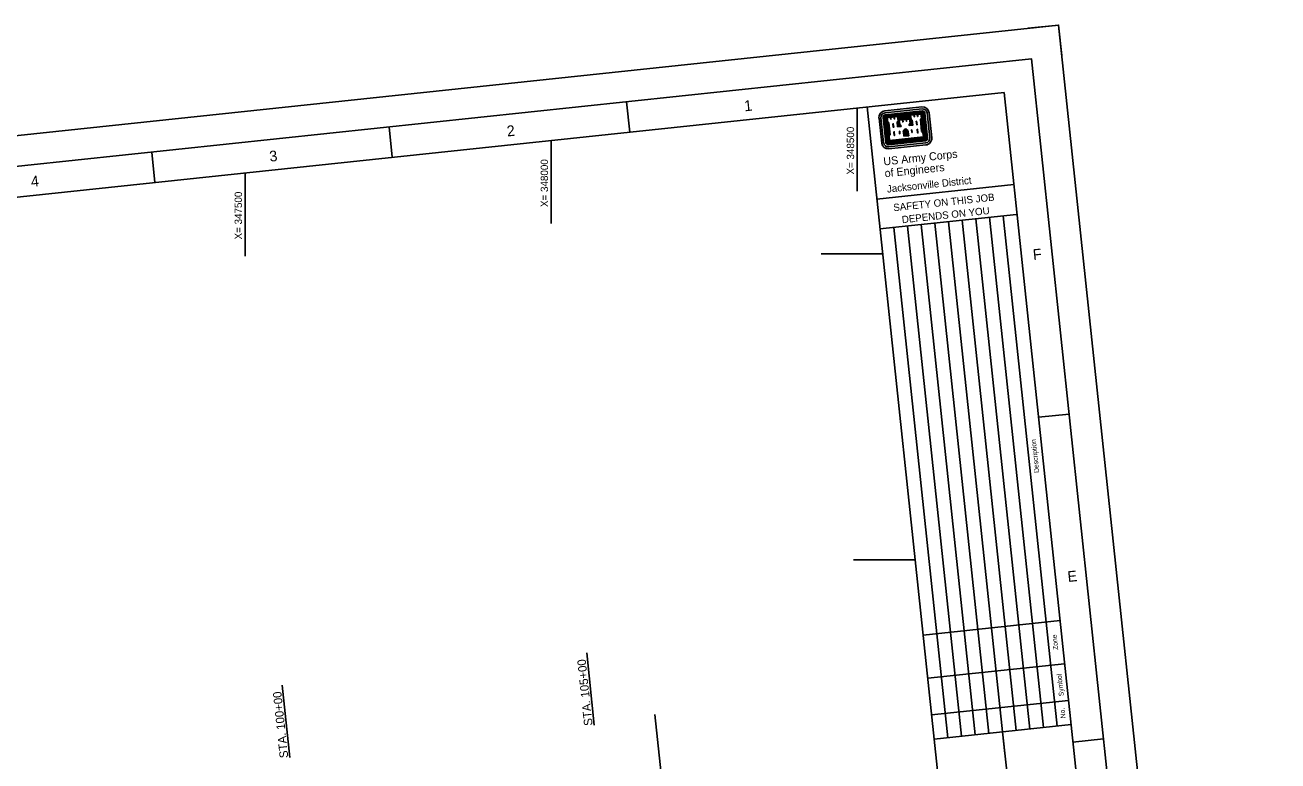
# Model space of a CAD drawing. Extents: x 344453 to 349187, y 1184529 to 1188374.
# Drawn here: x 347141 to 349187, y 1187172 to 1188374 of the extents above; entities that cross this region are included whole.
import ezdxf

# ---------------------------------------------------------------- set-up
doc = ezdxf.new("R2010")
doc.units = 0
for name, color, linetype in [('G-ANNO-NPLT', 7, 'Continuous'), ('G-ANNO-TEXT-LOGO', 7, 'Continuous'), ('G-ANNO-TEXT-TTLB', 7, 'Continuous'), ('G-ANNO-TTLB', 7, 'Continuous'), ('V-ALGN-TEXT', 7, 'Continuous'), ('V-ANNO-MATC', 7, 'Continuous'), ('V-TOPO-COOR-STAT', 7, 'Continuous')]:
    doc.layers.add(name, color=color, linetype=linetype)

msp = doc.modelspace()

# ---------------------------------------------------------------- linework, layer by layer
at = {"layer": 'G-ANNO-NPLT'}
msp.add_lwpolyline([(344453.5, 1187909.7), (348828.9, 1188373.5), (349187.3, 1184992.5), (344811.8, 1184528.7)], close=True, dxfattribs=at)
msp.add_lwpolyline([(348834.2, 1188323.8), (348828.9, 1188373.5), (348779.2, 1188368.3)], dxfattribs=at)
at = {"layer": 'G-ANNO-TEXT-LOGO'}
for p, q in [((348605.6, 1188239.9), (348545.2, 1188233.5)), ((348545.5, 1188230.3), (348606, 1188236.7)), ((348535.7, 1188221.7), (348540, 1188180.9)), ((348543.2, 1188181.3), (348538.8, 1188222)), ((348542.3, 1188222.4), (348546.6, 1188181.6)), ((348543.2, 1188222.5), (348547.5, 1188181.7)), ((348544, 1188222.6), (348548.3, 1188181.8)), ((348544.9, 1188222.7), (348549.2, 1188181.9)), ((348545.8, 1188222.8), (348550.1, 1188182)), ((348606.3, 1188233.3), (348545.9, 1188226.9)), ((348606.4, 1188232.4), (348546, 1188226)), ((348606.5, 1188231.5), (348546.1, 1188225.1)), ((348606.6, 1188230.7), (348546.1, 1188224.3)), ((348606.7, 1188229.8), (348546.2, 1188223.4)), ((348546.7, 1188222.9), (348551, 1188182.4)), ((348547.5, 1188222.9), (348551.7, 1188183.4)), ((348567.3, 1188224.8), (348585.8, 1188226.8)), ((348567.4, 1188223.9), (348585.9, 1188225.9)), ((348567.5, 1188223.2), (348586, 1188225.1)), ((348567.6, 1188222.3), (348586.1, 1188224.2)), ((348567.7, 1188221.4), (348586.2, 1188223.3)), ((348567.8, 1188220.6), (348586.3, 1188222.5)), ((348567.9, 1188219.7), (348586.3, 1188221.6)), ((348605, 1188219.4), (348607, 1188200.4)), ((348605.6, 1188229.1), (348609.8, 1188189.5)), ((348605.8, 1188220.3), (348608, 1188199.6)), ((348606.4, 1188229.2), (348610.7, 1188188.7)), ((348607.3, 1188229.3), (348611.6, 1188188.5)), ((348608.2, 1188229.4), (348612.5, 1188188.6)), ((348608.9, 1188229.5), (348613.3, 1188188.7)), ((348609.8, 1188229.6), (348614.2, 1188188.8)), ((348610.7, 1188229.6), (348615.1, 1188188.9)), ((348614.1, 1188230), (348618.4, 1188189.2)), ((348621.7, 1188189.6), (348617.4, 1188230.4)), ((348549.1, 1188214.4), (348551.3, 1188193.5)), ((348550.1, 1188213.6), (348552.1, 1188194.6)), ((348576.1, 1188191.9), (348575.4, 1188198.6)), ((348576.9, 1188192), (348576.2, 1188198.6)), ((348577.8, 1188192.1), (348577.1, 1188198.7)), ((348578.7, 1188192.2), (348578, 1188198.8)), ((348579.5, 1188192.2), (348578.8, 1188198.9)), ((348580.7, 1188192.4), (348580, 1188199)), ((348581.5, 1188192.5), (348580.8, 1188199.1)), ((348582.4, 1188192.6), (348581.7, 1188199.2)), ((348583.3, 1188192.6), (348582.6, 1188199.3)), ((348584.1, 1188192.7), (348583.4, 1188199.4)), ((348611.1, 1188187.9), (348550.7, 1188181.4)), ((348611.2, 1188187.1), (348550.8, 1188180.7)), ((348611.3, 1188186.2), (348550.9, 1188179.8)), ((348610.7, 1188188.7), (348551, 1188182.4)), ((348611.4, 1188185.3), (348551, 1188178.9)), ((348611.5, 1188184.5), (348551, 1188178.1)), ((348611.9, 1188181), (348551.4, 1188174.6)), ((348609.8, 1188189.5), (348551.7, 1188183.4)), ((348551.8, 1188171.3), (348612.2, 1188177.7)), ((348576.1, 1188191.9), (348584.1, 1188192.7))]:
    msp.add_line(p, q, dxfattribs=at)
for points in [[(348548.2, 1188223), (348549, 1188215.2), (348550.9, 1188213.6), (348552.9, 1188194.7), (348551.4, 1188192.7), (348552.3, 1188184), (348609, 1188190), (348608.1, 1188198.7), (348606.1, 1188200.3), (348604.1, 1188219.3), (348605.7, 1188221.2), (348604.9, 1188229), (348597.4, 1188228.2), (348591.6, 1188227.6), (348586.3, 1188227.1), (348587.1, 1188219.2), (348589.2, 1188217.7), (348589.9, 1188210.7), (348585.7, 1188210.3), (348585.7, 1188211), (348587.3, 1188213), (348586.4, 1188220.7), (348579, 1188219.9), (348573.2, 1188219.3), (348567.9, 1188218.8), (348568.8, 1188211), (348570.7, 1188209.4), (348570.8, 1188208.7), (348566.6, 1188208.3), (348565.9, 1188215.2), (348567.5, 1188217.1), (348566.7, 1188225), (348559.2, 1188224.2), (348553.5, 1188223.6), (348548.2, 1188223)], [(348549.1, 1188222.2), (348549.8, 1188215.6), (348551.8, 1188214), (348553.8, 1188194.4), (348552.2, 1188192.4), (348553, 1188185), (348608.1, 1188190.9), (348607.3, 1188198.2), (348605.3, 1188199.8), (348603.2, 1188219.5), (348604.9, 1188221.5), (348604.2, 1188228), (348598.8, 1188227.5), (348599.1, 1188224.4), (348598.6, 1188224.3), (348598.3, 1188227.4), (348593, 1188226.9), (348593.4, 1188223.8), (348593, 1188223.7), (348592.6, 1188226.8), (348587.3, 1188226.3), (348588, 1188219.7), (348589.9, 1188218.1), (348590.8, 1188210), (348585, 1188209.4), (348584.8, 1188211.3), (348586.4, 1188213.3), (348585.7, 1188219.9), (348580.4, 1188219.3), (348580.7, 1188216.2), (348580.3, 1188216.2), (348580, 1188219.2), (348574.6, 1188218.7), (348574.9, 1188215.6), (348574.4, 1188215.5), (348574.1, 1188218.6), (348568.8, 1188218.1), (348569.5, 1188211.5), (348571.5, 1188209.9), (348571.7, 1188208), (348565.9, 1188207.4), (348565.1, 1188215.5), (348566.7, 1188217.4), (348566, 1188224), (348560.7, 1188223.4), (348561, 1188220.4), (348560.5, 1188220.3), (348560.2, 1188223.4), (348554.8, 1188222.8), (348555.2, 1188219.7), (348554.8, 1188219.7), (348554.5, 1188222.8), (348549.1, 1188222.2)], [(348567.3, 1188215.5), (348566.8, 1188214.9), (348567.4, 1188209.3), (348569.3, 1188209.5), (348567.9, 1188210.6), (348567.4, 1188215.6)], [(348587.8, 1188217.7), (348588.3, 1188217.2), (348588.9, 1188211.5), (348587.1, 1188211.4), (348588.2, 1188212.8), (348587.7, 1188217.7)], [(348597, 1188216.5), (348597.7, 1188210.8), (348597.2, 1188210.7), (348596.5, 1188216.5), (348597, 1188216.5)], [(348558.4, 1188212.4), (348559, 1188206.7), (348559.6, 1188206.7), (348559, 1188212.5), (348558.4, 1188212.4)], [(348559.8, 1188199.2), (348560.4, 1188193.3), (348561, 1188193.4), (348560.4, 1188199.3), (348559.8, 1188199.2)], [(348568.9, 1188200.2), (348569.3, 1188196.1), (348569.8, 1188196.1), (348569.4, 1188200.2), (348568.9, 1188200.2)], [(348589.4, 1188202.3), (348589.8, 1188198.3), (348589.3, 1188198.2), (348588.9, 1188202.3), (348589.4, 1188202.3)], [(348598.4, 1188203.3), (348599.1, 1188197.4), (348598.6, 1188197.4), (348598, 1188203.3), (348598.4, 1188203.3)]]:
    msp.add_lwpolyline(points, dxfattribs=at)
for centre, major_axis, start_param, end_param in [((348606.7, 1188229.2), (10.7, 1.1), 6.283169, 7.853965), ((348606.7, 1188229.2), (7.45, 0.79), 6.28317, 7.853966), ((348546.3, 1188222.8), (10.7, 1.1), 1.57078, 3.141576), ((348546.3, 1188222.8), (7.45, 0.79), 1.57078, 3.141576), ((348546.3, 1188222.8), (4, 0.42), 1.57078, 3.141576), ((348546.3, 1188222.8), (3.13, 0.33), 1.57078, 3.141576), ((348546.3, 1188222.8), (2.27, 0.24), 1.57078, 3.141576), ((348546.3, 1188222.8), (1.41, 0.15), 1.57078, 3.141576), ((348546.3, 1188222.8), (0.543, 0.058), 1.57078, 3.141576), ((348606.7, 1188229.2), (4, 0.42), 6.283169, 7.853965), ((348606.7, 1188229.2), (3.13, 0.33), 6.283169, 7.853965), ((348606.7, 1188229.2), (2.27, 0.24), 6.283169, 7.853965), ((348606.7, 1188229.2), (1.41, 0.15), 6.283169, 7.853965), ((348606.7, 1188229.2), (0.543, 0.058), 6.283169, 7.853965), ((348580.9, 1188198.7), (-5.52, -0.59), 4.985832, 6.214359), ((348580.9, 1188198.7), (-4.66, -0.49), 4.947465, 6.21436), ((348580.9, 1188198.7), (-3.8, -0.4), 4.947465, 6.21436), ((348580.9, 1188198.7), (-2.93, -0.31), 4.947465, 6.21436), ((348577.9, 1188198.4), (2.07, 0.22), 0.068794, 1.335689), ((348577.9, 1188198.4), (2.93, 0.31), 0.068794, 1.335689), ((348577.9, 1188198.4), (3.8, 0.4), 0.068795, 1.335689), ((348577.9, 1188198.4), (4.66, 0.49), 0.068795, 1.335689), ((348580.9, 1188198.7), (-2.07, -0.22), 4.947465, 6.214359), ((348577.9, 1188198.4), (5.52, 0.59), 0.068795, 1.29842), ((348550.7, 1188182), (-10.7, -1.1), 6.28317, 7.853966), ((348550.7, 1188182), (-7.45, -0.79), 6.28317, 7.853966), ((348550.7, 1188182), (-4, -0.42), 6.28317, 7.853966), ((348550.7, 1188182), (-3.13, -0.33), 6.28317, 7.853966), ((348550.7, 1188182), (-2.27, -0.24), 6.28317, 7.853966), ((348550.7, 1188182), (-1.41, -0.15), 6.28317, 7.853966), ((348550.7, 1188182), (-0.543, -0.058), 6.28317, 7.853966), ((348611, 1188188.4), (0.543, 0.058), 4.712373, 6.28317), ((348611, 1188188.4), (1.41, 0.15), 4.712373, 6.28317), ((348611, 1188188.4), (2.27, 0.24), 4.712373, 6.28317), ((348611, 1188188.4), (4, 0.42), 4.712373, 6.28317), ((348611, 1188188.4), (3.13, 0.33), 4.712373, 6.28317), ((348611, 1188188.4), (-7.45, -0.79), 1.570781, 3.141577), ((348611, 1188188.4), (10.7, 1.1), 4.712373, 6.28317)]:
    msp.add_ellipse(centre, major_axis=major_axis, ratio=0.99964, start_param=start_param, end_param=end_param, dxfattribs=at)
at = {"layer": 'G-ANNO-TTLB'}
for p, q in [((348123.2, 1188248.4), (348128.5, 1188198.7)), ((348516.3, 1188239.8), (348853.6, 1185057.7)), ((347735.4, 1188207.3), (347740.6, 1188157.6)), ((347347.5, 1188166.2), (347352.8, 1188116.5)), ((348532.2, 1188089.4), (348756, 1188113.2)), ((348536.8, 1188040.5), (348760.5, 1188064.2)), ((348649.1, 1188052.4), (348737.4, 1187219.2)), ((348671.5, 1188054.8), (348759.8, 1187221.6)), ((348693.8, 1188057.2), (348782.2, 1187223.9)), ((348716.2, 1188059.6), (348804.5, 1187226.3)), ((348738.6, 1188061.9), (348826.9, 1187228.7)), ((348559.6, 1188042.9), (348647.9, 1187209.7)), ((348582, 1188045.3), (348670.3, 1187212.1)), ((348604.3, 1188047.7), (348692.7, 1187214.4)), ((348626.7, 1188050.1), (348715, 1187216.8)), ((348846, 1187738.3), (348796.3, 1187733)), ((348607.7, 1187377.4), (348831.4, 1187401.1)), ((348615.2, 1187306.7), (348838.9, 1187330.4)), ((348621.5, 1187247), (348845.3, 1187270.7)), ((348625.7, 1187207.4), (348849.5, 1187231.1)), ((348827.5, 1186364.4), (348737.6, 1187219.2)), ((348737.6, 1187219.2), (348741.3, 1187184)), ((348902.2, 1187208), (348852.5, 1187202.7))]:
    msp.add_line(p, q, dxfattribs=at)
for points in [[(344856.3, 1184583.7), (349132.3, 1185036.9), (348784.5, 1188318.5), (344508.5, 1187865.3)], [(348740, 1188263.6), (344638, 1187828.7), (344975.3, 1184646.6), (349077.3, 1185081.4)]]:
    msp.add_lwpolyline(points, close=True, dxfattribs=at)
at = {"layer": 'V-ALGN-TEXT'}
for p, q in [((348070.6, 1187230.3), (348058.1, 1187348.2)), ((347573.4, 1187177.6), (347560.9, 1187295.5))]:
    msp.add_line(p, q, dxfattribs=at)
at = {"layer": 'V-ANNO-MATC'}
msp.add_line((348306.4, 1185955), (348169.3, 1187247.7), dxfattribs=at)
at = {"layer": 'V-TOPO-COOR-STAT'}
for p, q in [((348500, 1188102.4), (348500, 1188238.1)), ((348000, 1188049.4), (348000, 1188185.1)), ((347500, 1187996.4), (347500, 1188132.1)), ((348441.1, 1188000), (348541.7, 1188000)), ((348494.1, 1187500), (348594.7, 1187500))]:
    msp.add_line(p, q, dxfattribs=at)

# ---------------------------------------------------------------- texts
at = {"layer": 'G-ANNO-TEXT-TTLB'}
for s, height, rotation, p in [('US Army Corps', 13.086, 6.0506, (348543.5, 1188144.2)), ('of Engineers', 13.086, 6.0506, (348545.5, 1188124.9)), ('Jacksonville District', 11.9, 6.0506, (348549.2, 1188099.8)), ('SAFETY ON THIS JOB', 11.9, 6.0506, (348559.6, 1188069.4)), ('DEPENDS ON YOU', 11.9, 6.0506, (348573.5, 1188049.8)), ('Description', 8, 96.0506, (348797.4, 1187642.6)), ('Zone', 8, 96.0506, (348828.4, 1187353.5)), ('Symbol', 8, 96.0506, (348837.6, 1187277.8)), ('No.', 8, 96.0506, (348840.4, 1187241.8))]:
    msp.add_text(s, height=height, rotation=rotation, dxfattribs=at).set_placement(p)
at = {"layer": 'G-ANNO-TTLB'}
for s, p in [('1', (348316.3, 1188232.6)), ('2', (347928.6, 1188191.5)), ('3', (347540.7, 1188150.3)), ('4', (347151.1, 1188109.1)), ('F', (348787.9, 1187989.8)), ('E', (348844.5, 1187463.9))]:
    msp.add_text(s, height=17.5, rotation=6.0506, dxfattribs=at).set_placement(p)
at = {"layer": 'V-ALGN-TEXT'}
for s, p in [('STA. 105+00', (348067.9, 1187229.9)), ('STA. 100+00', (347570.7, 1187177.2))]:
    msp.add_text(s, height=13.92, rotation=96.0506, dxfattribs=at).set_placement(p)
at = {"layer": 'V-TOPO-COOR-STAT'}
for s, p in [('X= 348500', (348495, 1188129.4)), ('X= 348000', (347995, 1188076.4)), ('X= 347500', (347495, 1188023.4))]:
    msp.add_text(s, height=12, rotation=90, dxfattribs=at).set_placement(p)

doc.saveas('drawing.dxf')
